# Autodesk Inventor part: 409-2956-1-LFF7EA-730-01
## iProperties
Created: 2010-06
Part Number: 409-2956-1-LFF7EA-730-01
Material: Sch40 CS PIPE SEAMLESS
Description: PIPE
Document SubType Name: Modeling
Designer: S. Boerckel
Engineer: Steve Boerckel
Mass: 829.412 g
Surface Area: 584.074 cm^2
Volume: 105.658 cm^3
Density: 7.85 g/cm^3
Cost Center: 1-1/2"
SMR: =<COST CENTER> - <Material>
Length: 8.065 in
Title: 1-1/2"
Author: S. Boerckel
Revision Number: A
Subject: DEMIN WATER FORWARDING PUMP SKID-7EA
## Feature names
1. Extrusion1
